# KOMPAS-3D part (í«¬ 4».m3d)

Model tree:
1. Эскиз:1
2. Операция выдавливания:1
     Расстояние 1 = 2
3. Эскиз:2
4. Операция выдавливания:2
     Расстояние 1 = 5
5. Эскиз:3
6. Операция выдавливания:3
     Расстояние 1 = 2
7. Эскиз:4
8. Операция выдавливания:4
     Расстояние 1 = 60
9. Эскиз:5
10. Операция выдавливания:5
     Расстояние 1 = 2
11. Эскиз:6
12. Операция выдавливания:6
     Расстояние 1 = 4.5
13. Эскиз:7
14. Операция выдавливания:7
     Расстояние 1 = 2
15. Скругление:1
     Радиус = 1
16. Скругление:2
     Радиус = 1
17. Эскиз:8
18. Вырезать элемент выдавливания:1
     Расстояние 1 = 10; Угол 1 = 35
19. Эскиз:9
20. Вырезать элемент выдавливания:2
     Расстояние 1 = 10; Угол 1 = 35
21. Эскиз:10
22. Вырезать элемент выдавливания:3
     Расстояние 2 = 22; Расстояние 1 = 22; Угол 1 = 35
23. Эскиз:11
24. Вырезать элемент выдавливания:4
     Расстояние 2 = 2; Расстояние 1 = 2
25. Эскиз:12
26. Вырезать элемент выдавливания:5
     Расстояние 2 = 2; Расстояние 1 = 2; Угол 1 = 35
27. Эскиз:13
28. Вырезать элемент выдавливания:6
     Расстояние 2 = 2; Расстояние 1 = 122
29. Эскиз:15
30. Операция выдавливания:9
     Расстояние 1 = 10; Расстояние 2 = 0.5
